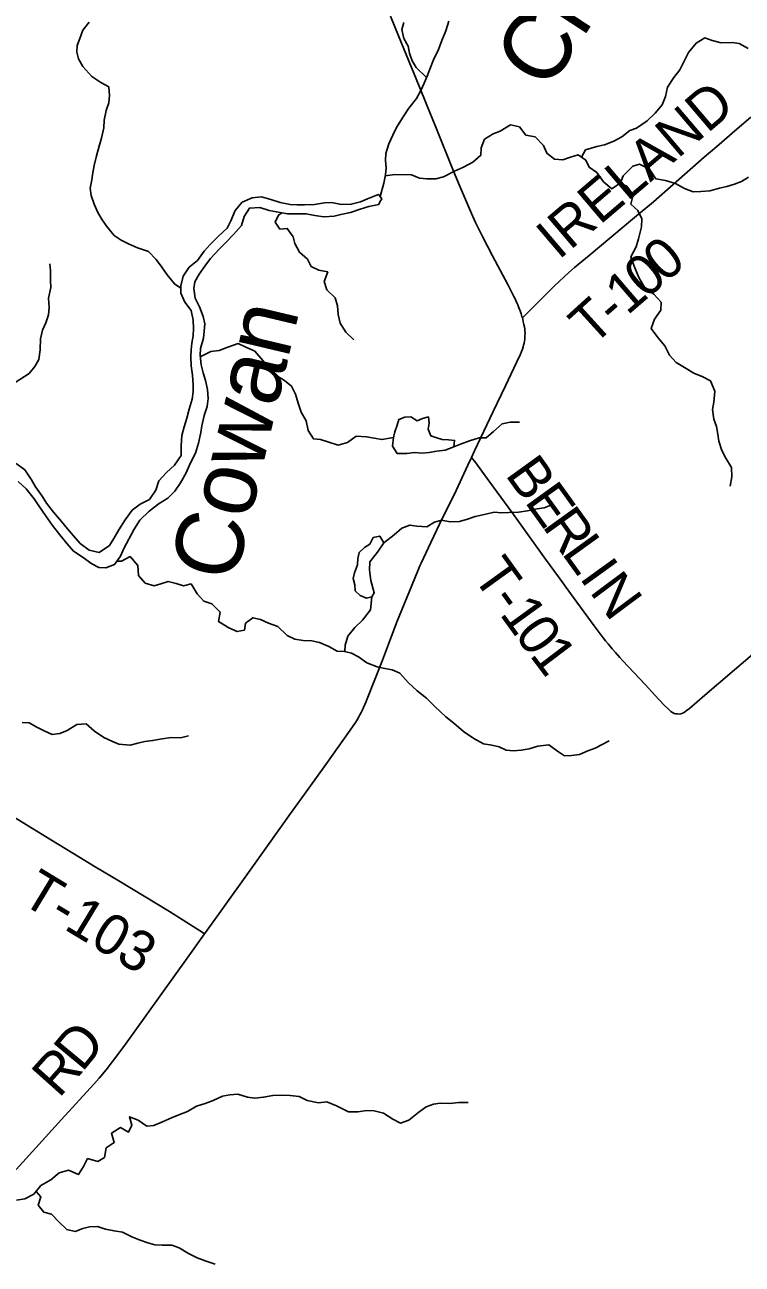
# Model space of a CAD drawing. Extents: x 0 to 34, y 0 to 22.
# Drawn here: x 5.891 to 6.899, y 17.375 to 19.116 of the extents above; entities that cross this region are included whole.
import ezdxf

# ---------------------------------------------------------------- set-up
doc = ezdxf.new("R2010")
doc.units = 0
for name, color, linetype in [('GM_X_County_Road', 7, 'Continuous'), ('GM_X_County_Road_Text', 7, 'Continuous'), ('GM_X_Major_River', 7, 'Continuous'), ('GM_X_Major_River_Text', 7, 'Continuous'), ('GM_X_Minor_Lake', 7, 'Continuous'), ('GM_X_Minor_River', 7, 'Continuous'), ('GM_X_Township_Road', 7, 'Continuous'), ('GM_X_Township_Road_Text', 7, 'Continuous')]:
    doc.layers.add(name, color=color, linetype=linetype)

msp = doc.modelspace()

# ---------------------------------------------------------------- linework, layer by layer
at = {"layer": 'GM_X_County_Road'}
for points in [[(6.5899, 18.7038), (6.5893, 18.7057), (6.5881, 18.7097), (6.5867, 18.7137), (6.5854, 18.7172), (6.5844, 18.7197), (6.5833, 18.7222), (6.5821, 18.7252), (6.5807, 18.7283), (6.5791, 18.7317), (6.5779, 18.7342), (6.5766, 18.7366), (6.5697, 18.7501), (6.5478, 18.7911), (6.5339, 18.8181), (6.527, 18.8321), (6.5253, 18.8353), (6.5241, 18.8381), (6.5183, 18.8506), (6.5014, 18.8899), (6.493, 18.91), (6.4681, 18.9717), (6.4554, 19.0027), (6.4447, 19.0293), (6.4159, 19.1), (6.4047, 19.1277)], [(6.5182, 18.5077), (6.5226, 18.5172), (6.5488, 18.5722), (6.5662, 18.6086), (6.5816, 18.6411), (6.587, 18.6529), (6.5885, 18.6567), (6.5898, 18.6598), (6.5908, 18.6633), (6.5916, 18.6657), (6.5922, 18.6686), (6.5928, 18.6711), (6.5931, 18.6739), (6.5935, 18.6765), (6.5935, 18.6793), (6.5936, 18.682), (6.5934, 18.6851), (6.5932, 18.6881), (6.5927, 18.6914), (6.5921, 18.6948), (6.5912, 18.6986), (6.5904, 18.702), (6.5899, 18.7038)], [(6.1434, 17.8386), (6.1446, 17.8403), (6.1663, 17.8706), (6.2074, 17.9283), (6.2316, 17.9622), (6.2642, 18.0076), (6.2899, 18.0434), (6.3139, 18.0767), (6.348, 18.1249), (6.3552, 18.1357), (6.3576, 18.1395), (6.3601, 18.1436), (6.3616, 18.1463), (6.3634, 18.1495), (6.3652, 18.1534), (6.3668, 18.1568), (6.3683, 18.1606), (6.3702, 18.1651), (6.3717, 18.1687), (6.3932, 18.2229), (6.4059, 18.2566), (6.4139, 18.2781), (6.4343, 18.3282), (6.4438, 18.3509), (6.4449, 18.3535), (6.4458, 18.3557), (6.4466, 18.3574), (6.4476, 18.3595), (6.4613, 18.3883), (6.4736, 18.414), (6.4861, 18.4397), (6.4938, 18.4553), (6.5131, 18.497), (6.5182, 18.5077)], [(5.8785, 17.5077), (5.9061, 17.5379), (5.9423, 17.578), (5.9877, 17.6274), (5.9951, 17.6357), (6.0049, 17.6477), (6.0141, 17.6594), (6.0298, 17.6803), (6.0455, 17.7019), (6.1189, 17.8044), (6.1434, 17.8386)]]:
    msp.add_lwpolyline(points, dxfattribs=at)
at = {"layer": 'GM_X_Major_River'}
for points in [[(6.3902, 18.8744), (6.395, 18.8933), (6.3975, 18.905), (6.3985, 18.9149), (6.3976, 18.9252), (6.3982, 18.9351), (6.4023, 18.9483), (6.4079, 18.9607), (6.413, 18.9712), (6.4213, 18.9851), (6.4303, 18.9986), (6.4409, 19.0121), (6.4472, 19.0234), (6.452, 19.0335), (6.456, 19.0437), (6.46, 19.0535), (6.4648, 19.0663), (6.472, 19.081), (6.4768, 19.0938), (6.4824, 19.107), (6.4865, 19.1206)], [(5.8785, 18.4993), (5.8908, 18.4903), (5.9, 18.4765), (5.9058, 18.4664), (5.915, 18.4533), (5.9213, 18.4437), (5.9312, 18.4309), (5.9423, 18.4178), (5.9509, 18.4077), (5.959, 18.3977), (5.9686, 18.3872), (5.9813, 18.3778), (5.9953, 18.3745), (6.0095, 18.384), (6.0158, 18.3942), (6.0226, 18.4062), (6.0316, 18.4201), (6.0414, 18.4336), (6.053, 18.4421), (6.066, 18.449), (6.0747, 18.4621), (6.0791, 18.475), (6.0896, 18.4869), (6.1008, 18.4969), (6.1103, 18.5108), (6.1106, 18.5241), (6.1112, 18.5385), (6.1146, 18.551), (6.1182, 18.5631), (6.1216, 18.5759), (6.1257, 18.5899), (6.1274, 18.6002), (6.1272, 18.6097), (6.1264, 18.6234), (6.1244, 18.6367), (6.1239, 18.6493), (6.1245, 18.6591), (6.1255, 18.6686), (6.1272, 18.6789), (6.1275, 18.6891), (6.1273, 18.7009), (6.1246, 18.7143), (6.1154, 18.7262), (6.1099, 18.7389), (6.1098, 18.7492), (6.1131, 18.7624), (6.1217, 18.7751), (6.1333, 18.7844), (6.1427, 18.7975), (6.1513, 18.8072), (6.1633, 18.8191), (6.175, 18.8299), (6.1801, 18.8404), (6.1861, 18.8548), (6.1962, 18.8663), (6.21, 18.8725), (6.2234, 18.8741), (6.2362, 18.8704), (6.2494, 18.866), (6.2634, 18.8634), (6.2736, 18.8628), (6.2839, 18.8626), (6.2979, 18.8634), (6.3116, 18.8654), (6.3215, 18.866), (6.3359, 18.8634), (6.3495, 18.8635), (6.3625, 18.867), (6.3721, 18.871), (6.384, 18.8761)], [(6.3902, 18.8744), (6.3876, 18.8773), (6.384, 18.8761)], [(6.3883, 18.8634), (6.3902, 18.8679), (6.3923, 18.8708), (6.3902, 18.8744)], [(5.8813, 18.4742), (5.8925, 18.4637), (5.9039, 18.4498), (5.9106, 18.4401), (5.9198, 18.4262), (5.9297, 18.4123), (5.94, 18.3992), (5.9504, 18.3864), (5.9593, 18.376), (5.9712, 18.3681), (5.9851, 18.3583), (5.9948, 18.3532), (6.0047, 18.3526), (6.0169, 18.3577), (6.0252, 18.3693), (6.03, 18.3802), (6.0442, 18.4073), (6.0525, 18.4196), (6.0656, 18.4323), (6.0796, 18.4434), (6.0915, 18.4508), (6.1016, 18.4604), (6.1094, 18.4724), (6.1173, 18.4863), (6.1229, 18.4995), (6.1304, 18.5138), (6.1349, 18.5278), (6.1379, 18.5429), (6.1393, 18.5524), (6.1426, 18.5668), (6.1471, 18.5796), (6.1485, 18.5906), (6.1476, 18.6035), (6.1445, 18.6161), (6.1413, 18.6269), (6.1385, 18.6379), (6.1369, 18.6517), (6.1378, 18.6611), (6.1416, 18.6755), (6.1429, 18.6854), (6.1435, 18.6956), (6.1411, 18.7059), (6.1361, 18.7197), (6.1303, 18.7316), (6.1283, 18.7454), (6.1297, 18.7548), (6.1356, 18.7653), (6.1438, 18.7766), (6.1516, 18.7874), (6.1641, 18.8009), (6.1738, 18.8102), (6.1839, 18.821), (6.1952, 18.8337), (6.1989, 18.8465), (6.2063, 18.8581), (6.2211, 18.859), (6.234, 18.8549), (6.2442, 18.8528), (6.26, 18.8502), (6.2726, 18.8499), (6.2859, 18.85), (6.298, 18.8478), (6.3108, 18.8461), (6.3253, 18.8469), (6.3348, 18.8493), (6.3485, 18.8521), (6.3619, 18.8568), (6.3741, 18.8603), (6.3883, 18.8634)]]:
    msp.add_lwpolyline(points, dxfattribs=at)
at = {"layer": 'GM_X_Minor_Lake'}
for points in [[(6.4934, 18.5227), (6.4947, 18.5318), (6.486, 18.5327), (6.4772, 18.5331), (6.4697, 18.5355), (6.461, 18.5383), (6.4573, 18.5474), (6.4589, 18.5561), (6.4579, 18.5649), (6.4495, 18.5627), (6.4419, 18.5594), (6.4332, 18.5648), (6.4245, 18.5645), (6.4161, 18.5612), (6.4141, 18.5532), (6.4105, 18.5438), (6.4086, 18.5358)], [(6.4086, 18.5358), (6.4073, 18.5237), (6.414, 18.5133), (6.4276, 18.5132), (6.4383, 18.5146), (6.4489, 18.5141), (6.4588, 18.5147), (6.4698, 18.5165), (6.4812, 18.5183), (6.4934, 18.5227)], [(6.3954, 18.3878), (6.3894, 18.3974), (6.3803, 18.3952), (6.3756, 18.3861), (6.368, 18.3813), (6.3607, 18.3745), (6.3587, 18.3658), (6.3582, 18.3571), (6.3539, 18.3458), (6.3519, 18.3378), (6.3545, 18.329), (6.3551, 18.3203), (6.3619, 18.3141), (6.3706, 18.3102), (6.3782, 18.312)], [(6.3782, 18.312), (6.3817, 18.3177), (6.3769, 18.3349), (6.3752, 18.3493), (6.3757, 18.3611), (6.3861, 18.375), (6.3954, 18.3878)]]:
    msp.add_lwpolyline(points, dxfattribs=at)
at = {"layer": 'GM_X_Minor_River'}
for points in [[(6.1098, 18.7455), (6.101, 18.7517), (6.0905, 18.7643), (6.0831, 18.7751), (6.0752, 18.7858), (6.0643, 18.7973), (6.0492, 18.8024), (6.0364, 18.8079), (6.0262, 18.8133), (6.0164, 18.8199), (6.0059, 18.8322), (5.9992, 18.8417), (5.9932, 18.8521), (5.9881, 18.8635), (5.984, 18.8761), (5.9826, 18.886), (5.9851, 18.8981), (5.9863, 18.9076), (5.9883, 18.9182), (5.9915, 18.9315), (5.9951, 18.9451), (5.9983, 18.9565), (6.0019, 18.9709), (6.0024, 18.9819), (6.0048, 18.9955), (6.0087, 19.0061), (6.0096, 19.0164), (6.0086, 19.0285), (5.9973, 19.0347), (5.9849, 19.0429), (5.9722, 19.0571), (5.9662, 19.0678), (5.9637, 19.0773), (5.9642, 19.0868), (5.9681, 19.0966), (5.972, 19.1083), (5.9812, 19.1193)], [(6.4552, 19.0418), (6.4406, 19.0555), (6.435, 19.065), (6.4313, 19.0757), (6.4295, 19.0856), (6.4232, 19.0963), (6.4203, 19.1089), (6.4231, 19.1187)], [(6.673, 18.9296), (6.6787, 18.9399), (6.6943, 18.9447), (6.7054, 18.9469), (6.7183, 18.952), (6.7294, 18.9584), (6.7409, 18.9673), (6.7504, 18.9706), (6.765, 18.9807), (6.7765, 18.9916), (6.7865, 19.0033), (6.7908, 19.015), (6.794, 19.0279), (6.8025, 19.0415), (6.811, 19.0524), (6.8172, 19.0648), (6.8231, 19.0769), (6.8342, 19.0897), (6.8461, 19.0976), (6.8567, 19.0936), (6.8692, 19.0905), (6.8847, 19.091), (6.8946, 19.0894), (6.907, 19.0824)], [(6.3972, 18.9037), (6.4107, 18.9054), (6.4342, 18.9051), (6.4455, 18.9001), (6.4554, 18.8992), (6.4683, 18.8994), (6.479, 18.9023), (6.4943, 18.9101), (6.5072, 18.9157), (6.5202, 18.9228), (6.5313, 18.9325), (6.5318, 18.9428), (6.5365, 18.9549), (6.5488, 18.9623), (6.5587, 18.9664), (6.5732, 18.975), (6.5857, 18.9725), (6.5947, 18.9607), (6.6079, 18.9582), (6.6196, 18.9463), (6.6244, 18.9352), (6.6349, 18.9268), (6.6467, 18.9259), (6.6562, 18.9292), (6.6684, 18.9328), (6.6789, 18.9255), (6.6837, 18.9156), (6.6943, 18.9082), (6.704, 18.8952), (6.7156, 18.8852), (6.7279, 18.8938), (6.7314, 18.9036), (6.7449, 18.9171), (6.7544, 18.9197), (6.7684, 18.9131), (6.7773, 18.8993), (6.7909, 18.8969), (6.8049, 18.8929), (6.8178, 18.8855), (6.8299, 18.8812), (6.8405, 18.8815), (6.8534, 18.8825), (6.8667, 18.8861), (6.877, 18.8887), (6.8877, 18.892), (6.8976, 18.8956), (6.9075, 18.9016)], [(6.7269, 18.8931), (6.7366, 18.8891), (6.7455, 18.8769), (6.7423, 18.8636), (6.7521, 18.8548), (6.7576, 18.8429), (6.7571, 18.8319), (6.7531, 18.8152), (6.7496, 18.8039), (6.7422, 18.7895), (6.747, 18.7766), (6.7533, 18.7609), (6.7618, 18.746), (6.7746, 18.7371), (6.7847, 18.726), (6.7846, 18.7146), (6.7757, 18.7022), (6.771, 18.6889), (6.78, 18.6763), (6.7901, 18.6648), (6.7967, 18.6518), (6.8061, 18.6414), (6.8178, 18.6344), (6.831, 18.6263), (6.8435, 18.6212), (6.8544, 18.6154), (6.8603, 18.6009), (6.859, 18.5854), (6.8569, 18.5751), (6.8587, 18.5618), (6.8627, 18.5515), (6.8645, 18.5408), (6.8659, 18.5306), (6.8703, 18.5176), (6.8759, 18.5069), (6.8837, 18.4939), (6.8843, 18.4806), (6.8819, 18.4677)], [(6.2517, 18.8515), (6.2472, 18.8484), (6.2425, 18.8382), (6.2492, 18.8286), (6.2595, 18.8296), (6.2677, 18.8178), (6.2702, 18.8083), (6.2769, 18.7964), (6.2878, 18.7864), (6.293, 18.7761), (6.3039, 18.771), (6.3164, 18.7686), (6.3113, 18.755), (6.315, 18.7435), (6.3266, 18.732), (6.3303, 18.721), (6.3309, 18.7088), (6.3338, 18.6966), (6.3416, 18.684), (6.3529, 18.6732)], [(5.8087, 18.5655), (5.8131, 18.5765), (5.8105, 18.5864), (5.8149, 18.5988), (5.8304, 18.6013), (5.8441, 18.6008), (5.8574, 18.6033), (5.8704, 18.6088), (5.8838, 18.6174), (5.8968, 18.6256), (5.9049, 18.6358), (5.9103, 18.6456), (5.9124, 18.6589), (5.9129, 18.6745), (5.9157, 18.6866), (5.9204, 18.6968), (5.924, 18.7081), (5.9248, 18.7184), (5.9242, 18.7317), (5.9271, 18.7465), (5.9268, 18.7571), (5.9266, 18.7704), (5.926, 18.7799)], [(6.1372, 18.6492), (6.1519, 18.6565), (6.164, 18.6579), (6.1759, 18.6627), (6.1903, 18.6679), (6.2005, 18.6632), (6.2137, 18.657), (6.225, 18.6443), (6.2351, 18.6313), (6.2456, 18.622), (6.2558, 18.6162), (6.2655, 18.6081), (6.2711, 18.597), (6.2748, 18.5841), (6.2788, 18.5715), (6.2862, 18.5593), (6.2887, 18.5459), (6.2962, 18.5341), (6.3064, 18.5332), (6.3166, 18.53), (6.331, 18.5253), (6.3439, 18.529), (6.3562, 18.5376), (6.371, 18.537), (6.3816, 18.535), (6.3926, 18.533), (6.4086, 18.5358), (6.4073, 18.5237), (6.414, 18.5133), (6.4276, 18.5132), (6.4383, 18.5146), (6.4489, 18.5141), (6.4588, 18.5147), (6.4698, 18.5165), (6.4812, 18.5183), (6.4934, 18.5227), (6.503, 18.5264), (6.5155, 18.5312), (6.5293, 18.5356), (6.5391, 18.5355), (6.5495, 18.5445), (6.5614, 18.5553), (6.5728, 18.5575), (6.5857, 18.5573)], [(6.3402, 18.2353), (6.3409, 18.2441), (6.3445, 18.257), (6.3545, 18.269), (6.3653, 18.2795), (6.3764, 18.2938), (6.3782, 18.312), (6.3817, 18.3177), (6.3769, 18.3349), (6.3752, 18.3493), (6.3757, 18.3611), (6.3861, 18.375), (6.3954, 18.3878), (6.4096, 18.3994), (6.4207, 18.4084), (6.4318, 18.4129), (6.4416, 18.4112), (6.4556, 18.4103), (6.4664, 18.417), (6.4763, 18.4196), (6.4884, 18.4175), (6.5017, 18.4178), (6.5127, 18.4214), (6.5234, 18.4251), (6.5386, 18.4283), (6.5504, 18.4309), (6.5606, 18.43), (6.5709, 18.4306), (6.5846, 18.4312), (6.5971, 18.433), (6.6108, 18.4359), (6.6203, 18.4369), (6.6322, 18.4417)], [(6.0203, 18.3624), (6.0265, 18.3624), (6.0387, 18.3687), (6.0496, 18.3561), (6.0506, 18.342), (6.0599, 18.3313), (6.0724, 18.3277), (6.0819, 18.3303), (6.0922, 18.3336), (6.1036, 18.3308), (6.1138, 18.3276), (6.1244, 18.3302), (6.133, 18.3164), (6.1424, 18.306), (6.1537, 18.3021), (6.1653, 18.2906), (6.1629, 18.2773), (6.1776, 18.2684), (6.1893, 18.2633), (6.1992, 18.2651), (6.2008, 18.275), (6.2112, 18.2828), (6.2218, 18.2804), (6.2331, 18.275), (6.2463, 18.2706), (6.2595, 18.2579), (6.27, 18.2525), (6.2818, 18.2509), (6.2939, 18.2503), (6.3049, 18.2479), (6.3177, 18.2425), (6.3298, 18.2359), (6.3401, 18.2354), (6.3499, 18.233), (6.3597, 18.2279), (6.3714, 18.2194), (6.3857, 18.2136), (6.3967, 18.2115), (6.4069, 18.2095), (6.4175, 18.2048), (6.4295, 18.1918), (6.4419, 18.1799), (6.4551, 18.1699), (6.4667, 18.1579), (6.4821, 18.1437), (6.4934, 18.1348), (6.5069, 18.1229), (6.5216, 18.1132), (6.5351, 18.1055), (6.5469, 18.1035), (6.5571, 18.1014), (6.5669, 18.0968), (6.5775, 18.0955), (6.5882, 18.0965), (6.5996, 18.0987), (6.6118, 18.1023), (6.627, 18.1041), (6.6394, 18.0952), (6.6492, 18.0886), (6.6587, 18.0893), (6.6701, 18.0907), (6.6819, 18.0955), (6.6922, 18.0995), (6.7022, 18.1047), (6.7117, 18.1099)], [(5.8868, 18.1357), (5.8966, 18.1352), (5.9076, 18.129), (5.9178, 18.1236), (5.9291, 18.1189), (5.9397, 18.1203), (5.95, 18.1244), (5.9638, 18.1326), (5.9771, 18.1335), (5.9884, 18.1235), (6.0019, 18.1143), (6.0129, 18.1092), (6.0227, 18.1049), (6.0386, 18.1036), (6.0496, 18.1065), (6.0592, 18.1087), (6.0702, 18.1101), (6.0839, 18.1126), (6.0964, 18.1143), (6.1093, 18.1138), (6.1208, 18.1167)], [(5.8789, 17.4647), (5.8907, 17.4664), (5.9033, 17.4727), (5.9133, 17.4851), (5.9271, 17.4929), (5.939, 17.503), (5.952, 17.5066), (5.966, 17.5004), (5.973, 17.5117), (5.9788, 17.523), (5.9932, 17.519), (6.0028, 17.5246), (6.0048, 17.5378), (6.0163, 17.5453), (6.0123, 17.5586), (6.025, 17.5668), (6.0363, 17.5598), (6.041, 17.57), (6.0377, 17.5814), (6.0502, 17.5767), (6.0622, 17.5686), (6.0721, 17.5692), (6.084, 17.5744), (6.0966, 17.5803), (6.1073, 17.5843), (6.1191, 17.5891), (6.1321, 17.5965), (6.1439, 17.6002), (6.1554, 17.6046), (6.1684, 17.6105), (6.179, 17.6126), (6.1901, 17.6133), (6.2037, 17.6093), (6.2139, 17.6076), (6.2261, 17.609), (6.239, 17.6115), (6.2512, 17.6121), (6.2637, 17.6115), (6.2762, 17.6099), (6.2876, 17.6044), (6.3035, 17.6012), (6.3149, 17.6025), (6.3289, 17.597), (6.3455, 17.5885), (6.3588, 17.5887), (6.3713, 17.5904), (6.3816, 17.5899), (6.3948, 17.5867), (6.4076, 17.5782), (6.4186, 17.5727), (6.4304, 17.5771), (6.4442, 17.5883), (6.4546, 17.5954), (6.4649, 17.5994), (6.4744, 17.6008)], [(6.4744, 17.6008), (6.4877, 17.6003), (6.5006, 17.6016), (6.5139, 17.6019)], [(5.9066, 17.4768), (5.9131, 17.4692), (5.9096, 17.4575), (5.9174, 17.4475), (5.928, 17.4447), (5.9385, 17.4339), (5.9497, 17.4232), (5.9615, 17.4207), (5.9722, 17.4248), (5.9817, 17.4269), (5.9927, 17.4275), (6.0041, 17.4236), (6.0162, 17.4212), (6.0279, 17.4195), (6.0411, 17.4129), (6.0528, 17.4082), (6.0634, 17.4046), (6.0736, 17.4018), (6.0839, 17.4013), (6.0972, 17.4015), (6.1078, 17.3976), (6.1206, 17.3898), (6.133, 17.3836), (6.1455, 17.3789), (6.158, 17.3745)]]:
    msp.add_lwpolyline(points, dxfattribs=at)
at = {"layer": 'GM_X_Township_Road'}
for points in [[(6.5899, 18.7038), (6.6013, 18.7153), (6.611, 18.725), (6.6214, 18.7356), (6.6352, 18.749), (6.6553, 18.7675), (6.6632, 18.7745), (6.6836, 18.7916), (6.7472, 18.8451), (6.774, 18.8672), (6.8016, 18.8914), (6.8455, 18.9296), (6.8629, 18.9446), (6.8916, 18.9693), (6.9108, 18.986)], [(6.5182, 18.5077), (6.5243, 18.5001), (6.5327, 18.4886), (6.5441, 18.473), (6.575, 18.431), (6.586, 18.4159), (6.6225, 18.365), (6.6404, 18.3403), (6.6576, 18.3167), (6.6909, 18.2711), (6.7033, 18.2547), (6.7067, 18.2504), (6.7102, 18.2459), (6.7159, 18.2392), (6.7206, 18.2339), (6.727, 18.2267), (6.7312, 18.2222), (6.7622, 18.1889), (6.7762, 18.174), (6.7893, 18.1599), (6.7946, 18.1545), (6.7985, 18.1512), (6.8006, 18.1498), (6.8031, 18.1484), (6.8055, 18.1477), (6.8078, 18.1475), (6.8104, 18.1474), (6.8126, 18.1477), (6.8147, 18.1485), (6.8171, 18.1496), (6.8202, 18.1517), (6.8248, 18.1551), (6.8464, 18.174), (6.8879, 18.2095), (6.9258, 18.2417)], [(6.1434, 17.8386), (6.1386, 17.8417), (6.1323, 17.8458), (6.0938, 17.8698), (6.0226, 17.9129), (5.9896, 17.9328), (5.9668, 17.9467), (5.928, 17.9702), (5.833, 18.0281), (5.7977, 18.0502), (5.7616, 18.0722), (5.7181, 18.0987), (5.7065, 18.1059), (5.6989, 18.1106)]]:
    msp.add_lwpolyline(points, dxfattribs=at)

# ---------------------------------------------------------------- texts
at = {"layer": 'GM_X_County_Road_Text'}
for s, rotation, p in [('D', 50.2446, (5.971, 17.6431)), ('R', 48.2556, (5.9386, 17.6067))]:
    msp.add_text(s, height=0.0568, rotation=rotation, dxfattribs=at).set_placement(p)
at = {"layer": 'GM_X_Major_River_Text'}
for s, rotation, p in [('Creek', 56.8513, (6.6249, 19.02)), ('Cowan', 76.6868, (6.1859, 18.3299))]:
    msp.add_text(s, height=0.0947, rotation=rotation, dxfattribs=at).set_placement(p)
at = {"layer": 'GM_X_Township_Road_Text'}
for s, height, rotation, p in [('IRELAND', 0.05682, 40.4157, (6.6408, 18.7844)), ('0', 0.0568, 40.5578, (6.7903, 18.7522)), ('0', 0.0568, 40.5838, (6.7637, 18.7294)), ('1', 0.0568, 40.6758, (6.7372, 18.7066)), ('T', 0.0568, 42.2685, (6.6884, 18.663)), ('-', 0.0568, 40.951, (6.7196, 18.6914)), ('B', 0.0568, 305.784, (6.5647, 18.4837)), ('E', 0.0568, 305.787, (6.592, 18.4459)), ('R', 0.0568, 305.784, (6.6168, 18.4114)), ('L', 0.0568, 305.787, (6.6441, 18.3735)), ('T', 0.0568, 305.7873, (6.5184, 18.3414)), ('I', 0.0568, 305.7986, (6.669, 18.339)), ('N', 0.0568, 306.7942, (6.6832, 18.3193)), ('-', 0.0568, 305.8029, (6.5432, 18.307)), ('1', 0.0568, 305.8784, (6.5569, 18.288)), ('0', 0.0568, 306.152, (6.5776, 18.2594)), ('1', 0.0568, 307.155, (6.5989, 18.2302)), ('T-103', 0.05682, 328.7973, (5.8827, 17.8833))]:
    msp.add_text(s, height=height, rotation=rotation, dxfattribs=at).set_placement(p)

doc.saveas('drawing.dxf')
